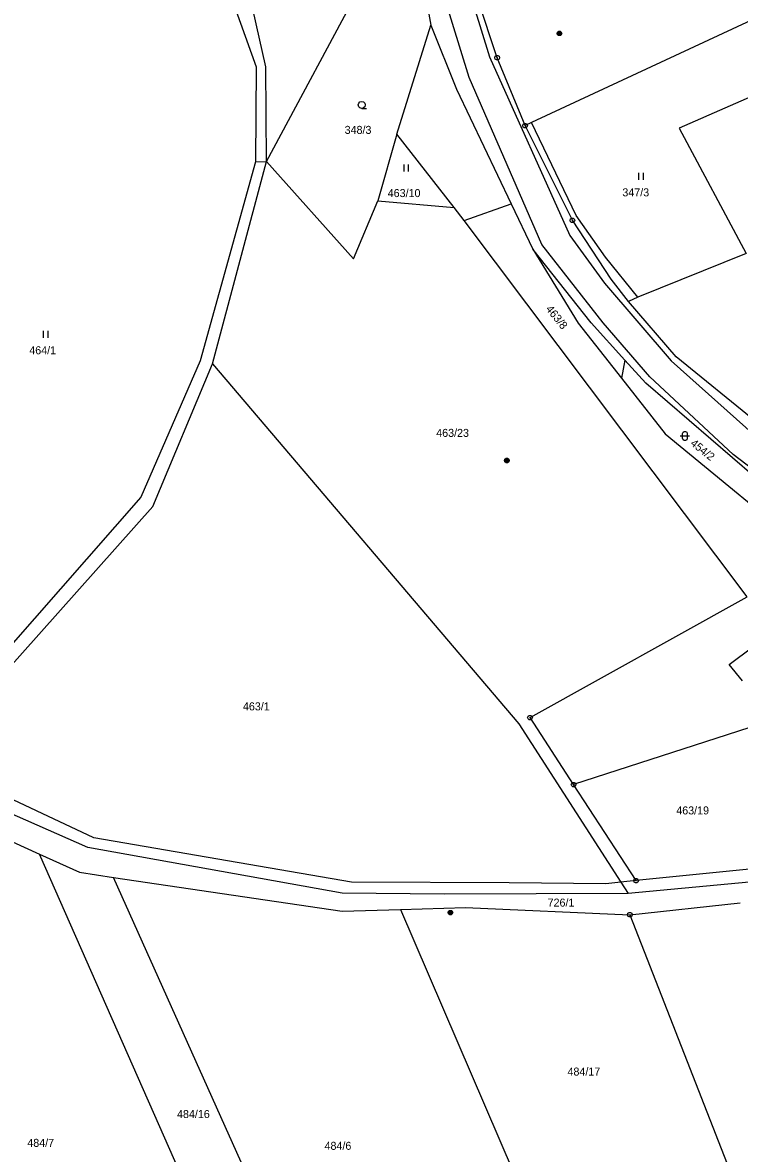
# Model space of a CAD drawing. Extents: x -694465 to -690527, y -983694 to -978978.
# Drawn here: x -693834.3 to -693682.1, y -981561.4 to -981321.2 of the extents above; entities that cross this region are included whole.
import ezdxf

# ---------------------------------------------------------------- set-up
doc = ezdxf.new("R2010")
doc.units = 0
for name, color, linetype in [('Vrstva 1', 7, 'Continuous'), ('Vrstva 18', 7, 'Continuous'), ('Vrstva 24', 7, 'Continuous'), ('Vrstva 25', 7, 'Continuous'), ('Vrstva 26', 7, 'Continuous')]:
    doc.layers.add(name, color=color, linetype=linetype)

msp = doc.modelspace()

# ---------------------------------------------------------------- linework, layer by layer
at = {"layer": 'Vrstva 1'}
for points in [[(-693739.52, -981332.86), (-693749.81, -981299.31)], [(-693744.37, -981298.61), (-693735.16, -981328.49)], [(-693733.54, -981328.69), (-693741.83, -981303.67)], [(-693792.68, -981308.227), (-693784.74, -981330.65)], [(-693782.66, -981330.63), (-693786.756, -981312.282)], [(-693782.52, -981350.77), (-693761.82, -981312)], [(-693749.28, -981312.744), (-693747.64, -981321.76)], [(-693679.57, -981320.71), (-693726.29, -981342.43)], [(-693754.82, -981344.95), (-693747.64, -981321.76)], [(-693747.64, -981321.76), (-693742.21, -981335.37)], [(-693735.16, -981328.49), (-693718.11, -981366.45)], [(-693784.74, -981330.65), (-693784.84, -981350.8)], [(-693782.52, -981350.77), (-693782.66, -981330.63)], [(-693727.64, -981343.12), (-693733.54, -981328.69)], [(-693724.09, -981368.35), (-693739.52, -981332.86)], [(-693742.21, -981335.37), (-693730.586, -981359.708)], [(-693673.26, -981334.18), (-693694.91, -981343.65)], [(-693726.29, -981342.43), (-693727.64, -981343.12)], [(-693716.81, -981362.22), (-693726.29, -981342.43)], [(-693754.82, -981344.95), (-693758.91, -981359.07)], [(-693742.65, -981360.48), (-693754.82, -981344.95)], [(-693717.59, -981363.23), (-693727.64, -981343.12)], [(-693694.91, -981343.65), (-693680.73, -981370.26)], [(-693784.84, -981350.8), (-693796.61, -981393.08)], [(-693793.97, -981393.69), (-693782.52, -981350.77)], [(-693784.84, -981350.8), (-693782.52, -981350.77)], [(-693782.52, -981350.77), (-693764.05, -981371.44)], [(-693764.05, -981371.44), (-693758.91, -981359.07)], [(-693758.91, -981359.07), (-693742.65, -981360.48)], [(-693740.536, -981363.292), (-693730.586, -981359.708)], [(-693730.586, -981359.708), (-693725.99, -981369.33)], [(-693740.536, -981363.292), (-693742.65, -981360.48)], [(-693710.54, -981371.07), (-693716.81, -981362.22)], [(-693680.46, -981443.19), (-693740.536, -981363.292)], [(-693709.37, -981375.7), (-693717.59, -981363.23)], [(-693718.11, -981366.45), (-693710.8, -981376.6)], [(-693725.99, -981369.33), (-693716.38, -981385.06)], [(-693713.58, -981385.03), (-693725.99, -981369.33)], [(-693711.02, -981385), (-693724.09, -981368.35)], [(-693703.69, -981379.54), (-693710.54, -981371.07)], [(-693680.73, -981370.26), (-693703.69, -981379.54)], [(-693710.8, -981376.6), (-693696.61, -981393.07)], [(-693705.71, -981380.46), (-693709.37, -981375.7)], [(-693703.69, -981379.54), (-693705.71, -981380.46)], [(-693695.58, -981392.26), (-693705.71, -981380.46)], [(-693716.38, -981385.06), (-693707.185, -981396.76)], [(-693706.471, -981392.9), (-693713.58, -981385.03)], [(-693701.14, -981396.48), (-693711.02, -981385)], [(-693796.61, -981393.08), (-693809.17, -981422.01)], [(-693706.471, -981392.9), (-693707.185, -981396.76)], [(-693702, -981397.85), (-693706.471, -981392.9)], [(-693696.61, -981393.07), (-693678.76, -981409.03)], [(-693661.43, -981419.98), (-693695.58, -981392.26)], [(-693806.67, -981423.98), (-693793.97, -981393.69)], [(-693793.97, -981393.69), (-693728.94, -981470.16)], [(-693707.185, -981396.76), (-693697.88, -981408.6)], [(-693669.78, -981425.56), (-693702, -981397.85)], [(-693683.44, -981413), (-693701.14, -981396.48)], [(-693697.88, -981408.6), (-693665.67, -981435.03)], [(-693668.83, -981424.19), (-693683.44, -981413)], [(-693809.17, -981422.01), (-693848.91, -981467.31)], [(-693854.56, -981477.77), (-693806.67, -981423.98)], [(-693726.58, -981468.85), (-693680.46, -981443.19)], [(-693684.29, -981457.54), (-693674.55, -981450.3)], [(-693681.44, -981461.02), (-693684.29, -981457.54)], [(-693728.94, -981470.16), (-693707.33, -981503.82)], [(-693717.33, -981483.08), (-693726.58, -981468.85)], [(-693677.72, -981470.25), (-693717.33, -981483.08)], [(-693819.18, -981494.41), (-693854.56, -981477.77)], [(-693820.43, -981496.42), (-693856.93, -981480.36)], [(-693859.6, -981484.7), (-693830.69, -981497.86)], [(-693704.07, -981503.49), (-693717.33, -981483.08)], [(-693766.49, -981506.13), (-693820.43, -981496.42)], [(-693764.51, -981503.79), (-693819.18, -981494.41)], [(-693784.41, -981602.81), (-693830.69, -981497.86)], [(-693830.69, -981497.86), (-693822.22, -981501.72)], [(-693637.76, -981499.81), (-693705.77, -981506.25)], [(-693675.71, -981500.61), (-693704.07, -981503.49)], [(-693822.22, -981501.72), (-693815.02, -981502.79)], [(-693772.17, -981598.3), (-693815.02, -981502.79)], [(-693815.02, -981502.79), (-693766.45, -981509.97)], [(-693730.99, -981503.97), (-693764.51, -981503.79)], [(-693710.51, -981504.14), (-693730.99, -981503.97)], [(-693707.33, -981503.82), (-693710.51, -981504.14)], [(-693704.07, -981503.49), (-693707.33, -981503.82)], [(-693707.33, -981503.82), (-693705.77, -981506.25)], [(-693744.81, -981506.37), (-693766.49, -981506.13)], [(-693705.77, -981506.25), (-693744.81, -981506.37)], [(-693705.4, -981510.72), (-693681.999, -981508.221)], [(-693766.45, -981509.97), (-693754.09, -981509.6)], [(-693754.09, -981509.6), (-693740.3, -981509.19)], [(-693754.09, -981509.6), (-693724.1, -981579.44)], [(-693740.3, -981509.19), (-693705.4, -981510.72)], [(-693705.4, -981510.72), (-693682.95, -981568.17)]]:
    msp.add_lwpolyline(points, dxfattribs=at)
at = {"layer": 'Vrstva 24'}
for points in [[(-693733.386, -981328.214), (-693733.136, -981328.396), (-693733.04, -981328.69), (-693733.136, -981328.984), (-693733.386, -981329.166), (-693733.694, -981329.166), (-693733.944, -981328.984), (-693734.04, -981328.69), (-693733.944, -981328.396), (-693733.694, -981328.214)], [(-693727.486, -981342.644), (-693727.236, -981342.826), (-693727.14, -981343.12), (-693727.236, -981343.414), (-693727.486, -981343.596), (-693727.794, -981343.596), (-693728.044, -981343.414), (-693728.14, -981343.12), (-693728.044, -981342.826), (-693727.794, -981342.644)], [(-693717.436, -981362.754), (-693717.186, -981362.936), (-693717.09, -981363.23), (-693717.186, -981363.524), (-693717.436, -981363.706), (-693717.744, -981363.706), (-693717.994, -981363.524), (-693718.09, -981363.23), (-693717.994, -981362.936), (-693717.744, -981362.754)], [(-693726.426, -981468.374), (-693726.176, -981468.556), (-693726.08, -981468.85), (-693726.176, -981469.144), (-693726.426, -981469.326), (-693726.734, -981469.326), (-693726.984, -981469.144), (-693727.08, -981468.85), (-693726.984, -981468.556), (-693726.734, -981468.374)], [(-693717.176, -981482.604), (-693716.926, -981482.786), (-693716.83, -981483.08), (-693716.926, -981483.374), (-693717.176, -981483.556), (-693717.484, -981483.556), (-693717.734, -981483.374), (-693717.83, -981483.08), (-693717.734, -981482.786), (-693717.484, -981482.604)], [(-693703.916, -981503.014), (-693703.666, -981503.196), (-693703.57, -981503.49), (-693703.666, -981503.784), (-693703.916, -981503.966), (-693704.224, -981503.966), (-693704.474, -981503.784), (-693704.57, -981503.49), (-693704.474, -981503.196), (-693704.224, -981503.014)], [(-693705.246, -981510.244), (-693704.996, -981510.426), (-693704.9, -981510.72), (-693704.996, -981511.014), (-693705.246, -981511.196), (-693705.554, -981511.196), (-693705.804, -981511.014), (-693705.9, -981510.72), (-693705.804, -981510.426), (-693705.554, -981510.244)]]:
    msp.add_lwpolyline(points, close=True, dxfattribs=at)
for points in [[(-693733.659, -981328.69), (-693733.42, -981328.69)], [(-693727.759, -981343.12), (-693727.52, -981343.12)], [(-693717.709, -981363.23), (-693717.47, -981363.23)], [(-693726.699, -981468.85), (-693726.46, -981468.85)], [(-693717.449, -981483.08), (-693717.21, -981483.08)], [(-693704.189, -981503.49), (-693703.95, -981503.49)], [(-693705.519, -981510.72), (-693705.28, -981510.72)]]:
    msp.add_lwpolyline(points, dxfattribs=at)
at = {"layer": 'Vrstva 25'}
for points in [[(-693762.3, -981339.47), (-693762.675, -981339.369), (-693762.949, -981339.095), (-693763.05, -981338.72), (-693762.949, -981338.345), (-693762.675, -981338.071), (-693762.3, -981337.97), (-693761.925, -981338.071), (-693761.651, -981338.345), (-693761.55, -981338.72), (-693761.651, -981339.095), (-693761.925, -981339.369), (-693762.3, -981339.47), (-693761.3, -981339.471)], [(-693753.4, -981351.39), (-693753.4, -981352.89)], [(-693752.4, -981352.89), (-693752.4, -981351.39)], [(-693703.52, -981353.15), (-693703.52, -981354.65)], [(-693702.52, -981354.65), (-693702.52, -981353.15)], [(-693829.9, -981386.7), (-693829.9, -981388.2)], [(-693828.9, -981388.2), (-693828.9, -981386.7)], [(-693694.7, -981409.03), (-693692.7, -981409.03)]]:
    msp.add_lwpolyline(points, dxfattribs=at)
msp.add_lwpolyline([(-693694.2, -981408.53), (-693694.105, -981408.236), (-693693.855, -981408.054), (-693693.545, -981408.054), (-693693.295, -981408.236), (-693693.2, -981408.53), (-693693.2, -981409.53), (-693693.295, -981409.824), (-693693.545, -981410.006), (-693693.855, -981410.006), (-693694.105, -981409.824), (-693694.2, -981409.53)], close=True, dxfattribs=at)
at = {"layer": 'Vrstva 26'}
for points in [[(-693720.495, -981323.054), (-693720.185, -981323.054), (-693719.935, -981323.236), (-693719.84, -981323.53), (-693719.935, -981323.824), (-693720.185, -981324.006), (-693720.495, -981324.006), (-693720.745, -981323.824), (-693720.84, -981323.53), (-693720.745, -981323.236), (-693720.495, -981323.054), (-693720.46, -981323.09), (-693720.22, -981323.09), (-693720.06, -981323.17), (-693720.62, -981323.17), (-693720.7, -981323.25), (-693719.98, -981323.25), (-693719.98, -981323.33), (-693720.7, -981323.33), (-693720.742, -981323.41), (-693719.94, -981323.411), (-693719.9, -981323.49), (-693720.78, -981323.49), (-693720.78, -981323.57), (-693719.9, -981323.57), (-693719.931, -981323.649), (-693720.745, -981323.649), (-693720.739, -981323.73), (-693719.931, -981323.73), (-693719.98, -981323.81), (-693720.7, -981323.81), (-693720.62, -981323.89), (-693720.06, -981323.89), (-693720.168, -981323.969), (-693720.508, -981323.969)], [(-693731.655, -981413.784), (-693731.345, -981413.784), (-693731.095, -981413.966), (-693731, -981414.26), (-693731.095, -981414.554), (-693731.345, -981414.736), (-693731.655, -981414.736), (-693731.905, -981414.554), (-693732, -981414.26), (-693731.905, -981413.966), (-693731.655, -981413.784), (-693731.62, -981413.82), (-693731.38, -981413.82), (-693731.22, -981413.9), (-693731.78, -981413.9), (-693731.86, -981413.98), (-693731.14, -981413.98), (-693731.14, -981414.06), (-693731.86, -981414.06), (-693731.902, -981414.14), (-693731.1, -981414.141), (-693731.06, -981414.22), (-693731.94, -981414.22), (-693731.94, -981414.3), (-693731.06, -981414.3), (-693731.091, -981414.379), (-693731.905, -981414.379), (-693731.899, -981414.46), (-693731.091, -981414.46), (-693731.14, -981414.54), (-693731.86, -981414.54), (-693731.78, -981414.62), (-693731.22, -981414.62), (-693731.328, -981414.699), (-693731.668, -981414.699)], [(-693731.655, -981413.784), (-693731.345, -981413.784), (-693731.095, -981413.966), (-693731, -981414.26), (-693731.095, -981414.554), (-693731.345, -981414.736), (-693731.655, -981414.736), (-693731.905, -981414.554), (-693732, -981414.26), (-693731.905, -981413.966), (-693731.655, -981413.784), (-693731.62, -981413.82), (-693731.38, -981413.82), (-693731.22, -981413.9), (-693731.78, -981413.9), (-693731.86, -981413.98), (-693731.14, -981413.98), (-693731.14, -981414.06), (-693731.86, -981414.06), (-693731.902, -981414.14), (-693731.1, -981414.141), (-693731.06, -981414.22), (-693731.94, -981414.22), (-693731.94, -981414.3), (-693731.06, -981414.3), (-693731.091, -981414.379), (-693731.905, -981414.379), (-693731.899, -981414.46), (-693731.091, -981414.46), (-693731.14, -981414.54), (-693731.86, -981414.54), (-693731.78, -981414.62), (-693731.22, -981414.62), (-693731.328, -981414.699), (-693731.668, -981414.699)], [(-693743.635, -981509.794), (-693743.325, -981509.794), (-693743.075, -981509.976), (-693742.98, -981510.27), (-693743.075, -981510.564), (-693743.325, -981510.746), (-693743.635, -981510.746), (-693743.885, -981510.564), (-693743.98, -981510.27), (-693743.885, -981509.976), (-693743.635, -981509.794), (-693743.6, -981509.83), (-693743.36, -981509.83), (-693743.2, -981509.91), (-693743.76, -981509.91), (-693743.84, -981509.99), (-693743.12, -981509.99), (-693743.12, -981510.07), (-693743.84, -981510.07), (-693743.882, -981510.15), (-693743.08, -981510.151), (-693743.04, -981510.23), (-693743.92, -981510.23), (-693743.92, -981510.31), (-693743.04, -981510.31), (-693743.071, -981510.389), (-693743.885, -981510.389), (-693743.879, -981510.47), (-693743.071, -981510.47), (-693743.12, -981510.55), (-693743.84, -981510.55), (-693743.76, -981510.63), (-693743.2, -981510.63), (-693743.308, -981510.709), (-693743.648, -981510.709)]]:
    msp.add_lwpolyline(points, dxfattribs=at)

# ---------------------------------------------------------------- texts
at = {"layer": 'Vrstva 18'}
for s, p in [('348/3', (-693765.934, -981344.87)), ('463/10', (-693756.788, -981358.29)), ('347/3', (-693706.977, -981358.14)), ('464/1', (-693832.875, -981391.68)), ('463/23', (-693746.493, -981409.23)), ('463/1', (-693787.522, -981467.32)), ('463/19', (-693695.533, -981489.42)), ('726/1', (-693722.849, -981509)), ('484/17', (-693718.623, -981544.89)), ('484/16', (-693801.513, -981553.91)), ('484/7', (-693833.293, -981560.03)), ('484/6', (-693770.2, -981560.66))]:
    msp.add_text(s, height=1.7, dxfattribs=at).set_placement(p)
for s, rotation, p in [('463/8', 308.70966, (-693723.334, -981382.107)), ('454/2', 321.31473, (-693692.674, -981410.859))]:
    msp.add_text(s, height=1.7, rotation=rotation, dxfattribs=at).set_placement(p)

doc.saveas('drawing.dxf')
